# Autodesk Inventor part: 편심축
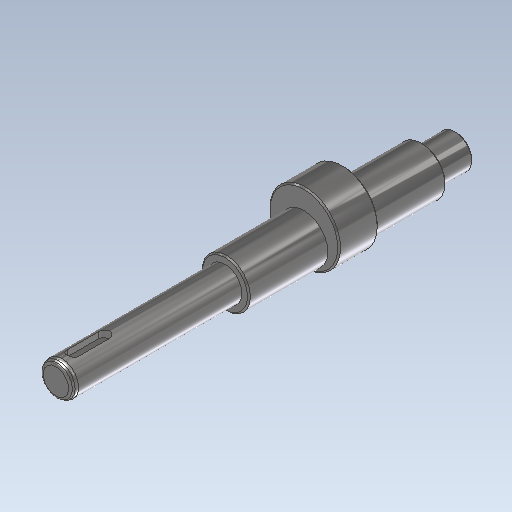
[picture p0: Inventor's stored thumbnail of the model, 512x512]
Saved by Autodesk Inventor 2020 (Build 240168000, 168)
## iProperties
Created: 2016-02
Part Number: 편심축
Material: 강철, 연강
Document SubType Name: Modeling
Designer: mduedu
Density: 1 g/cm^3
Appearance: 반광택
Author: mduedu
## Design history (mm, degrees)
sketch "스케치1"
  geometry: C1 r 6 at (0, 0); 1 further point
  constraints: 1 centre point, 1 coincident
  dimensions: "d0" = 12 diameter of C1
extrude "돌출1" new body sketch "스케치1" distance "d1" = 142; taper "d2" = 0 deg
chamfer "모따기1" distance "d3" = 0.5; stored, may be unused: second distance "d4" = 2, angle "d5" = 45 deg
node "작업 평면2"
sketch "스케치3"
  geometry: C1 r 8.5 at (0, 0); 1 further point
  constraints: 1 centre point, 1 coincident
  dimensions: "d12" = 17 diameter of C1
extrude "돌출3" join sketch "스케치3" distance "d13" = 70; taper "d14" = 0 deg
node "작업 평면3"
sketch "스케치4"
  geometry: L1 (0, 142)-(0, 0); L2 (-2, 136)-(-2, 125); L3 (2, 125)-(2, 136); L4 (6, 142)-(-6, 142) reference; A1 r 2 centre (0, 136) between (2, 136) and (-2, 136); A2 r 2 centre (0, 125) between (-2, 125) and (2, 125)
  constraints: 6 end point, 4 point on circle, 4 tangent, 2 centre point, 2 point on line, 1 midpoint, 1 parallel
  dimensions: "d15" = 4 distance between parallel lines of L2 L3; "d18" = 15 dimension on A2 A1; "d36" = 4 distance edge to line of A1 L4
extrude "돌출4" cut sketch "스케치4" distance "d19" = 2.5; taper "d20" = 0 deg
node "작업 평면1"
sketch "스케치2"
  geometry: C1 r 12.5 at (0, 3); C2 r 8.5 at (0, 0) reference; 1 further point
  constraints: 1 centre point, 1 vertical alignment
  dimensions: "d7" = 25 diameter of C1; "d32" = 3 distance of C1.centre point (0, 0)
extrude "돌출2" join sketch "스케치2" stored distance "d8" = 14; taper "d9" = 0 deg
sketch "스케치5"
  geometry: L1 (6, 82)-(6, 142) reference; L2 (-6, 82)-(-6, 142) reference; L3 (6, 115)-(-6, 115); L4 (6, 116.5)-(4.5, 115); L5 (6, 116.5)-(6, 115); L6 (4.5, 115)-(6, 115); L7 (6, 142)-(-6, 142) reference; 1 further point
  constraints: 8 end point, 4 point on line, 2 collinear, 1 perpendicular
  dimensions: "d22" = 3 diameter of L4.start L3; "d24" = 45 deg angle of L3 L4; "d37" = 27 distance between parallel lines of L7 L3
revolve "회전1" sketch "스케치5" stored, may be unused: angle "d25" = 90 deg
sketch "스케치6"
  geometry: L1 (6, 116.5)-(4.5, 115) reference; L2 (6, 113.5)-(4.5, 115) reference; 2 further points
  constraints: 1 coincident
node "작업 평면4"
chamfer "모따기2" distance "d33" = 0.5; stored, may be unused: second distance "d34" = 2, angle "d35" = 45 deg
sketch "스케치8"
  geometry: L1 (5.1, 142)-(6, 140.441); L2 (6, 82)-(6, 142) reference; L3 (6, 142)-(-6, 142) reference; L4 (0, 142)-(0, 86.696); 1 further point
  constraints: 4 end point, 2 point on line, 1 midpoint, 1 perpendicular
  dimensions: "d38" = 10.2 diameter of L1.start L4; "d43" = 30 deg angle of L2 L1
revolve "회전2" sketch "스케치8" stored, may be unused: angle "d45" = 90 deg
fillet "모깎기1" dims "d46" = 2, "d47" = 1
node "솔리드1"
other parameters: "d6" = -47, "d11" = -12, "d26" = 28
